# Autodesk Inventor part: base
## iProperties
Shininess: 64.0
Length Units: 11272
Angle Units: 11279
Time Units: 11290
Mass Units: 11286
Length Display Precision: 3
Angle Display Precision: 2
Compacted: True
Part Number: base
Document SubType Name: Modeling
Created: 2002-11
Designer: Elise Moss
Density: 0.0
Volumn: 0.0
Area: 0.0
PropertySet Name: Model Information
Control State: 0
Master: False
Checked Out: False
Author: Elise Moss
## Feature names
1. Base1
